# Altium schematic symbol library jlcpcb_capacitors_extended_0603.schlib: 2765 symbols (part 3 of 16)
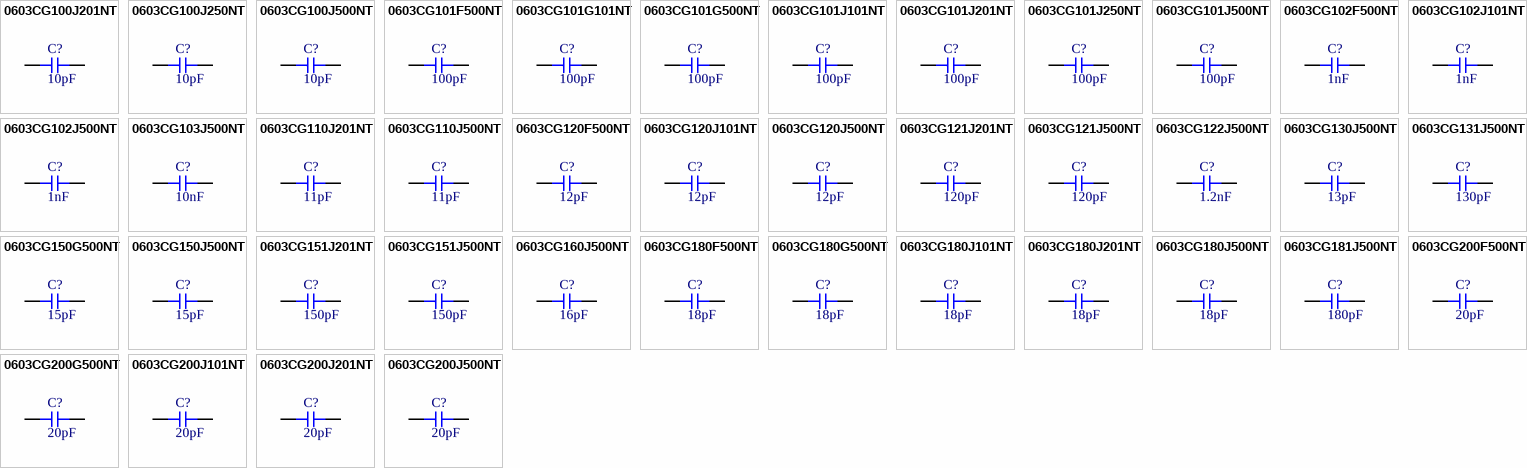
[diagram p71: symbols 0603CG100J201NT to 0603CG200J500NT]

## 0603CG200G500NT
designator C?  Capacitance: 20pF  (hidden comment: *)
Capacitor, Ceramic (MLCC), 20pF, ±2%, 50V, C0G, ±2%, SMD 0603; Manufacturer: FH(Guangdong Fenghua Advanced Tech); Manufacturer Part Number: 0603CG200G500NT
footprint CAP-0603 (0603 (1608M) Capacitor)
pins: 1, 2

## 0603CG200J101NT
designator C?  Capacitance: 20pF  (hidden comment: *)
Capacitor, Ceramic (MLCC), 20pF, ±5%, 100V, C0G, ±5%, SMD 0603; Manufacturer: FH(Guangdong Fenghua Advanced Tech); Manufacturer Part Number: 0603CG200J101NT
footprint CAP-0603 (0603 (1608M) Capacitor)
pins: 1, 2

## 0603CG200J201NT
designator C?  Capacitance: 20pF  (hidden comment: *)
Capacitor, Ceramic (MLCC), 20pF, ±5%, 200V, C0G, ±5%, SMD 0603; Manufacturer: FH(Guangdong Fenghua Advanced Tech); Manufacturer Part Number: 0603CG200J201NT
footprint CAP-0603 (0603 (1608M) Capacitor)
pins: 1, 2

## 0603CG200J500NT
designator C?  Capacitance: 20pF  (hidden comment: *)
Capacitor, Ceramic (MLCC), 20pF, ±5%, 50V, C0G, ±5%, SMD 0603; Manufacturer: FH(Guangdong Fenghua Advanced Tech); Manufacturer Part Number: 0603CG200J500NT
footprint CAP-0603 (0603 (1608M) Capacitor)
pins: 1, 2

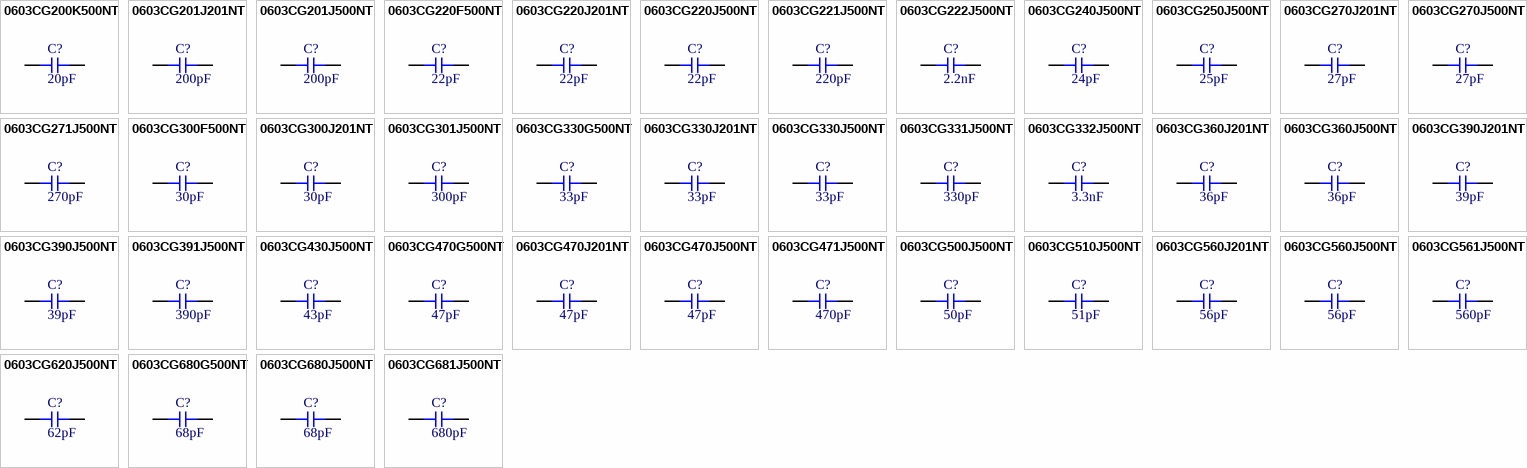
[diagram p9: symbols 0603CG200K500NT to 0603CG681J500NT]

## 0603CG200K500NT
designator C?  Capacitance: 20pF  (hidden comment: *)
Capacitor, Ceramic (MLCC), 20pF, ±10%, 50V, ±10%, SMD 0603; Manufacturer: FH (Guangdong Fenghua Advanced Tech); Manufacturer Part Number: 0603CG200K500NT
footprint CAP-0603 (0603 (1608M) Capacitor)
pins: 1, 2

## 0603CG201J201NT
designator C?  Capacitance: 200pF  (hidden comment: *)
Capacitor, Ceramic (MLCC), 200pF, ±5%, 200V, C0G, ±5%, SMD 0603; Manufacturer: FH(Guangdong Fenghua Advanced Tech); Manufacturer Part Number: 0603CG201J201NT
footprint CAP-0603 (0603 (1608M) Capacitor)
pins: 1, 2

## 0603CG201J500NT
designator C?  Capacitance: 200pF  (hidden comment: *)
Capacitor, Ceramic (MLCC), 200pF, ±5%, 50V, C0G, ±5%, SMD 0603; Manufacturer: FH(Guangdong Fenghua Advanced Tech); Manufacturer Part Number: 0603CG201J500NT
footprint CAP-0603 (0603 (1608M) Capacitor)
pins: 1, 2

## 0603CG220F500NT
designator C?  Capacitance: 22pF  (hidden comment: *)
Capacitor, Ceramic (MLCC), 22pF, ±1%, 50V, C0G, ±1%, SMD 0603; Manufacturer: FH(Guangdong Fenghua Advanced Tech); Manufacturer Part Number: 0603CG220F500NT
footprint CAP-0603 (0603 (1608M) Capacitor)
pins: 1, 2

## 0603CG220J201NT
designator C?  Capacitance: 22pF  (hidden comment: *)
Capacitor, Ceramic (MLCC), 22pF, ±5%, 200V, C0G, ±5%, SMD 0603; Manufacturer: FH(Guangdong Fenghua Advanced Tech); Manufacturer Part Number: 0603CG220J201NT
footprint CAP-0603 (0603 (1608M) Capacitor)
pins: 1, 2

## 0603CG220J500NT
designator C?  Capacitance: 22pF  (hidden comment: *)
Capacitor, Ceramic (MLCC), 22pF, ±5%, 50V, C0G, ±5%, SMD 0603; Manufacturer: FH(Guangdong Fenghua Advanced Tech); Manufacturer Part Number: 0603CG220J500NT
footprint CAP-0603 (0603 (1608M) Capacitor)
pins: 1, 2

## 0603CG221J500NT
designator C?  Capacitance: 220pF  (hidden comment: *)
Capacitor, Ceramic (MLCC), 220pF, ±5%, 50V, C0G, ±5%, SMD 0603; Manufacturer: FH(Guangdong Fenghua Advanced Tech); Manufacturer Part Number: 0603CG221J500NT
footprint CAP-0603 (0603 (1608M) Capacitor)
pins: 1, 2

## 0603CG222J500NT
designator C?  Capacitance: 2.2nF  (hidden comment: *)
Capacitor, Ceramic (MLCC), 2.2nF, ±5%, 50V, C0G, ±5%, SMD 0603; Manufacturer: FH(Guangdong Fenghua Advanced Tech); Manufacturer Part Number: 0603CG222J500NT
footprint CAP-0603 (0603 (1608M) Capacitor)
pins: 1, 2

## 0603CG240J500NT
designator C?  Capacitance: 24pF  (hidden comment: *)
Capacitor, Ceramic (MLCC), 24pF, ±5%, 50V, C0G, ±5%, SMD 0603; Manufacturer: FH(Guangdong Fenghua Advanced Tech); Manufacturer Part Number: 0603CG240J500NT
footprint CAP-0603 (0603 (1608M) Capacitor)
pins: 1, 2

## 0603CG250J500NT
designator C?  Capacitance: 25pF  (hidden comment: *)
Capacitor, Ceramic (MLCC), 25pF, ±5%, 50V, C0G, ±5%, SMD 0603; Manufacturer: FH(Guangdong Fenghua Advanced Tech); Manufacturer Part Number: 0603CG250J500NT
footprint CAP-0603 (0603 (1608M) Capacitor)
pins: 1, 2

## 0603CG270J201NT
designator C?  Capacitance: 27pF  (hidden comment: *)
Capacitor, Ceramic (MLCC), 27pF, ±5%, 200V, C0G, ±5%, SMD 0603; Manufacturer: FH(Guangdong Fenghua Advanced Tech); Manufacturer Part Number: 0603CG270J201NT
footprint CAP-0603 (0603 (1608M) Capacitor)
pins: 1, 2

## 0603CG270J500NT
designator C?  Capacitance: 27pF  (hidden comment: *)
Capacitor, Ceramic (MLCC), 27pF, ±5%, 50V, C0G, ±5%, SMD 0603; Manufacturer: FH(Guangdong Fenghua Advanced Tech); Manufacturer Part Number: 0603CG270J500NT
footprint CAP-0603 (0603 (1608M) Capacitor)
pins: 1, 2

## 0603CG271J500NT
designator C?  Capacitance: 270pF  (hidden comment: *)
Capacitor, Ceramic (MLCC), 270pF, ±5%, 50V, C0G, ±5%, SMD 0603; Manufacturer: FH(Guangdong Fenghua Advanced Tech); Manufacturer Part Number: 0603CG271J500NT
footprint CAP-0603 (0603 (1608M) Capacitor)
pins: 1, 2

## 0603CG300F500NT
designator C?  Capacitance: 30pF  (hidden comment: *)
Capacitor, Ceramic (MLCC), 30pF, ±1%, 50V, C0G, ±1%, SMD 0603; Manufacturer: FH(Guangdong Fenghua Advanced Tech); Manufacturer Part Number: 0603CG300F500NT
footprint CAP-0603 (0603 (1608M) Capacitor)
pins: 1, 2

## 0603CG300J201NT
designator C?  Capacitance: 30pF  (hidden comment: *)
Capacitor, Ceramic (MLCC), 30pF, ±5%, 200V, C0G, ±5%, SMD 0603; Manufacturer: FH(Guangdong Fenghua Advanced Tech); Manufacturer Part Number: 0603CG300J201NT
footprint CAP-0603 (0603 (1608M) Capacitor)
pins: 1, 2

## 0603CG301J500NT
designator C?  Capacitance: 300pF  (hidden comment: *)
Capacitor, Ceramic (MLCC), 300pF, ±5%, 50V, C0G, ±5%, SMD 0603; Manufacturer: FH(Guangdong Fenghua Advanced Tech); Manufacturer Part Number: 0603CG301J500NT
footprint CAP-0603 (0603 (1608M) Capacitor)
pins: 1, 2

## 0603CG330G500NT
designator C?  Capacitance: 33pF  (hidden comment: *)
Capacitor, Ceramic (MLCC), 33pF, ±2%, 50V, C0G, ±2%, SMD 0603; Manufacturer: FH(Guangdong Fenghua Advanced Tech); Manufacturer Part Number: 0603CG330G500NT
footprint CAP-0603 (0603 (1608M) Capacitor)
pins: 1, 2

## 0603CG330J201NT
designator C?  Capacitance: 33pF  (hidden comment: *)
Capacitor, Ceramic (MLCC), 33pF, ±5%, 200V, C0G, ±5%, SMD 0603; Manufacturer: FH(Guangdong Fenghua Advanced Tech); Manufacturer Part Number: 0603CG330J201NT
footprint CAP-0603 (0603 (1608M) Capacitor)
pins: 1, 2

## 0603CG330J500NT
designator C?  Capacitance: 33pF  (hidden comment: *)
Capacitor, Ceramic (MLCC), 33pF, ±5%, 50V, C0G, ±5%, SMD 0603; Manufacturer: FH(Guangdong Fenghua Advanced Tech); Manufacturer Part Number: 0603CG330J500NT
footprint CAP-0603 (0603 (1608M) Capacitor)
pins: 1, 2

## 0603CG331J500NT
designator C?  Capacitance: 330pF  (hidden comment: *)
Capacitor, Ceramic (MLCC), 330pF, ±5%, 50V, C0G, ±5%, SMD 0603; Manufacturer: FH(Guangdong Fenghua Advanced Tech); Manufacturer Part Number: 0603CG331J500NT
footprint CAP-0603 (0603 (1608M) Capacitor)
pins: 1, 2

## 0603CG332J500NT
designator C?  Capacitance: 3.3nF  (hidden comment: *)
Capacitor, Ceramic (MLCC), 3.3nF, ±5%, 50V, C0G, ±5%, SMD 0603; Manufacturer: FH(Guangdong Fenghua Advanced Tech); Manufacturer Part Number: 0603CG332J500NT
footprint CAP-0603 (0603 (1608M) Capacitor)
pins: 1, 2

## 0603CG360J201NT
designator C?  Capacitance: 36pF  (hidden comment: *)
Capacitor, Ceramic (MLCC), 36pF, ±5%, 200V, C0G, ±5%, SMD 0603; Manufacturer: FH(Guangdong Fenghua Advanced Tech); Manufacturer Part Number: 0603CG360J201NT
footprint CAP-0603 (0603 (1608M) Capacitor)
pins: 1, 2

## 0603CG360J500NT
designator C?  Capacitance: 36pF  (hidden comment: *)
Capacitor, Ceramic (MLCC), 36pF, ±5%, 50V, C0G, ±5%, SMD 0603; Manufacturer: FH(Guangdong Fenghua Advanced Tech); Manufacturer Part Number: 0603CG360J500NT
footprint CAP-0603 (0603 (1608M) Capacitor)
pins: 1, 2

## 0603CG390J201NT
designator C?  Capacitance: 39pF  (hidden comment: *)
Capacitor, Ceramic (MLCC), 39pF, ±5%, 200V, C0G, ±5%, SMD 0603; Manufacturer: FH(Guangdong Fenghua Advanced Tech); Manufacturer Part Number: 0603CG390J201NT
footprint CAP-0603 (0603 (1608M) Capacitor)
pins: 1, 2

## 0603CG390J500NT
designator C?  Capacitance: 39pF  (hidden comment: *)
Capacitor, Ceramic (MLCC), 39pF, ±5%, 50V, C0G, ±5%, SMD 0603; Manufacturer: FH(Guangdong Fenghua Advanced Tech); Manufacturer Part Number: 0603CG390J500NT
footprint CAP-0603 (0603 (1608M) Capacitor)
pins: 1, 2

## 0603CG391J500NT
designator C?  Capacitance: 390pF  (hidden comment: *)
Capacitor, Ceramic (MLCC), 390pF, ±5%, 50V, C0G, ±5%, SMD 0603; Manufacturer: FH(Guangdong Fenghua Advanced Tech); Manufacturer Part Number: 0603CG391J500NT
footprint CAP-0603 (0603 (1608M) Capacitor)
pins: 1, 2

## 0603CG430J500NT
designator C?  Capacitance: 43pF  (hidden comment: *)
Capacitor, Ceramic (MLCC), 43pF, ±5%, 50V, C0G, ±5%, SMD 0603; Manufacturer: FH(Guangdong Fenghua Advanced Tech); Manufacturer Part Number: 0603CG430J500NT
footprint CAP-0603 (0603 (1608M) Capacitor)
pins: 1, 2

## 0603CG470G500NT
designator C?  Capacitance: 47pF  (hidden comment: *)
Capacitor, Ceramic (MLCC), 47pF, ±2%, 50V, C0G, ±2%, SMD 0603; Manufacturer: FH(Guangdong Fenghua Advanced Tech); Manufacturer Part Number: 0603CG470G500NT
footprint CAP-0603 (0603 (1608M) Capacitor)
pins: 1, 2

## 0603CG470J201NT
designator C?  Capacitance: 47pF  (hidden comment: *)
Capacitor, Ceramic (MLCC), 47pF, ±5%, 200V, C0G, ±5%, SMD 0603; Manufacturer: FH(Guangdong Fenghua Advanced Tech); Manufacturer Part Number: 0603CG470J201NT
footprint CAP-0603 (0603 (1608M) Capacitor)
pins: 1, 2

## 0603CG470J500NT
designator C?  Capacitance: 47pF  (hidden comment: *)
Capacitor, Ceramic (MLCC), 47pF, ±5%, 50V, C0G, ±5%, SMD 0603; Manufacturer: FH(Guangdong Fenghua Advanced Tech); Manufacturer Part Number: 0603CG470J500NT
footprint CAP-0603 (0603 (1608M) Capacitor)
pins: 1, 2

## 0603CG471J500NT
designator C?  Capacitance: 470pF  (hidden comment: *)
Capacitor, Ceramic (MLCC), 470pF, ±5%, 50V, C0G, ±5%, SMD 0603; Manufacturer: FH(Guangdong Fenghua Advanced Tech); Manufacturer Part Number: 0603CG471J500NT
footprint CAP-0603 (0603 (1608M) Capacitor)
pins: 1, 2

## 0603CG500J500NT
designator C?  Capacitance: 50pF  (hidden comment: *)
Capacitor, Ceramic (MLCC), 50pF, ±5%, 50V, C0G, ±5%, SMD 0603; Manufacturer: FH(Guangdong Fenghua Advanced Tech); Manufacturer Part Number: 0603CG500J500NT
footprint CAP-0603 (0603 (1608M) Capacitor)
pins: 1, 2

## 0603CG510J500NT
designator C?  Capacitance: 51pF  (hidden comment: *)
Capacitor, Ceramic (MLCC), 51pF, ±5%, 50V, C0G, ±5%, SMD 0603; Manufacturer: FH(Guangdong Fenghua Advanced Tech); Manufacturer Part Number: 0603CG510J500NT
footprint CAP-0603 (0603 (1608M) Capacitor)
pins: 1, 2

## 0603CG560J201NT
designator C?  Capacitance: 56pF  (hidden comment: *)
Capacitor, Ceramic (MLCC), 56pF, ±5%, 200V, C0G, ±5%, SMD 0603; Manufacturer: FH(Guangdong Fenghua Advanced Tech); Manufacturer Part Number: 0603CG560J201NT
footprint CAP-0603 (0603 (1608M) Capacitor)
pins: 1, 2

## 0603CG560J500NT
designator C?  Capacitance: 56pF  (hidden comment: *)
Capacitor, Ceramic (MLCC), 56pF, ±5%, 50V, C0G, ±5%, SMD 0603; Manufacturer: FH(Guangdong Fenghua Advanced Tech); Manufacturer Part Number: 0603CG560J500NT
footprint CAP-0603 (0603 (1608M) Capacitor)
pins: 1, 2

## 0603CG561J500NT
designator C?  Capacitance: 560pF  (hidden comment: *)
Capacitor, Ceramic (MLCC), 560pF, ±5%, 50V, C0G, ±5%, SMD 0603; Manufacturer: FH(Guangdong Fenghua Advanced Tech); Manufacturer Part Number: 0603CG561J500NT
footprint CAP-0603 (0603 (1608M) Capacitor)
pins: 1, 2

## 0603CG620J500NT
designator C?  Capacitance: 62pF  (hidden comment: *)
Capacitor, Ceramic (MLCC), 62pF, ±5%, 50V, C0G, ±5%, SMD 0603; Manufacturer: FH(Guangdong Fenghua Advanced Tech); Manufacturer Part Number: 0603CG620J500NT
footprint CAP-0603 (0603 (1608M) Capacitor)
pins: 1, 2

## 0603CG680G500NT
designator C?  Capacitance: 68pF  (hidden comment: *)
Capacitor, Ceramic (MLCC), 68pF, ±2%, 50V, C0G, ±2%, SMD 0603; Manufacturer: FH(Guangdong Fenghua Advanced Tech); Manufacturer Part Number: 0603CG680G500NT
footprint CAP-0603 (0603 (1608M) Capacitor)
pins: 1, 2

## 0603CG680J500NT
designator C?  Capacitance: 68pF  (hidden comment: *)
Capacitor, Ceramic (MLCC), 68pF, ±5%, 50V, C0G, ±5%, SMD 0603; Manufacturer: FH(Guangdong Fenghua Advanced Tech); Manufacturer Part Number: 0603CG680J500NT
footprint CAP-0603 (0603 (1608M) Capacitor)
pins: 1, 2

## 0603CG681J500NT
designator C?  Capacitance: 680pF  (hidden comment: *)
Capacitor, Ceramic (MLCC), 680pF, ±5%, 50V, C0G, ±5%, SMD 0603; Manufacturer: FH(Guangdong Fenghua Advanced Tech); Manufacturer Part Number: 0603CG681J500NT
footprint CAP-0603 (0603 (1608M) Capacitor)
pins: 1, 2

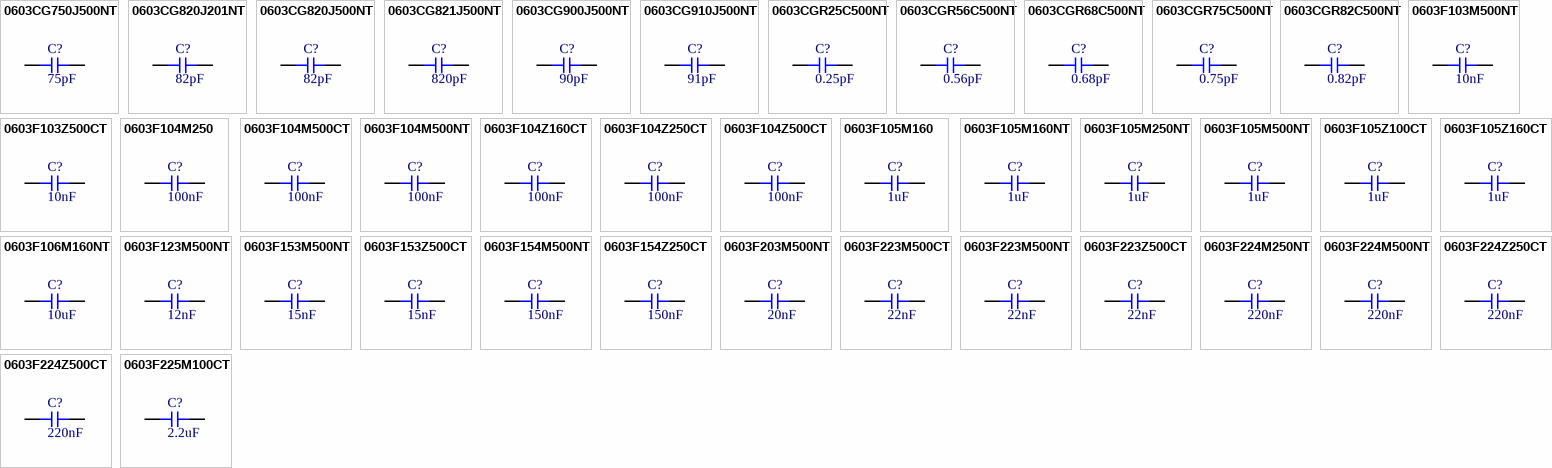
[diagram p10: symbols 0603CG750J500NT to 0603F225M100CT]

## 0603CG750J500NT
designator C?  Capacitance: 75pF  (hidden comment: *)
Capacitor, Ceramic (MLCC), 75pF, ±5%, 50V, C0G, ±5%, SMD 0603; Manufacturer: FH(Guangdong Fenghua Advanced Tech); Manufacturer Part Number: 0603CG750J500NT
footprint CAP-0603 (0603 (1608M) Capacitor)
pins: 1, 2

## 0603CG820J201NT
designator C?  Capacitance: 82pF  (hidden comment: *)
Capacitor, Ceramic (MLCC), 82pF, ±5%, 200V, C0G, ±5%, SMD 0603; Manufacturer: FH(Guangdong Fenghua Advanced Tech); Manufacturer Part Number: 0603CG820J201NT
footprint CAP-0603 (0603 (1608M) Capacitor)
pins: 1, 2

## 0603CG820J500NT
designator C?  Capacitance: 82pF  (hidden comment: *)
Capacitor, Ceramic (MLCC), 82pF, ±5%, 50V, C0G, ±5%, SMD 0603; Manufacturer: FH(Guangdong Fenghua Advanced Tech); Manufacturer Part Number: 0603CG820J500NT
footprint CAP-0603 (0603 (1608M) Capacitor)
pins: 1, 2

## 0603CG821J500NT
designator C?  Capacitance: 820pF  (hidden comment: *)
Capacitor, Ceramic (MLCC), 820pF, ±5%, 50V, C0G, ±5%, SMD 0603; Manufacturer: FH(Guangdong Fenghua Advanced Tech); Manufacturer Part Number: 0603CG821J500NT
footprint CAP-0603 (0603 (1608M) Capacitor)
pins: 1, 2

## 0603CG900J500NT
designator C?  Capacitance: 90pF  (hidden comment: *)
Capacitor, Ceramic (MLCC), 90pF, ±5%, 50V, C0G, ±5%, SMD 0603; Manufacturer: FH(Guangdong Fenghua Advanced Tech); Manufacturer Part Number: 0603CG900J500NT
footprint CAP-0603 (0603 (1608M) Capacitor)
pins: 1, 2

## 0603CG910J500NT
designator C?  Capacitance: 91pF  (hidden comment: *)
Capacitor, Ceramic (MLCC), 91pF, ±5%, 50V, C0G, ±5%, SMD 0603; Manufacturer: FH(Guangdong Fenghua Advanced Tech); Manufacturer Part Number: 0603CG910J500NT
footprint CAP-0603 (0603 (1608M) Capacitor)
pins: 1, 2

## 0603CGR25C500NT
designator C?  Capacitance: 0.25pF  (hidden comment: *)
Capacitor, Ceramic (MLCC), 0.25pF, ±0.25pF, 50V, C0G, ±0.25pF, SMD 0603; Manufacturer: FH(Guangdong Fenghua Advanced Tech); Manufacturer Part Number: 0603CGR25C500NT
footprint CAP-0603 (0603 (1608M) Capacitor)
pins: 1, 2

## 0603CGR56C500NT
designator C?  Capacitance: 0.56pF  (hidden comment: *)
Capacitor, Ceramic (MLCC), 0.56pF, ±0.25pF, 50V, C0G, ±0.25pF, SMD 0603; Manufacturer: FH(Guangdong Fenghua Advanced Tech); Manufacturer Part Number: 0603CGR56C500NT
footprint CAP-0603 (0603 (1608M) Capacitor)
pins: 1, 2

## 0603CGR68C500NT
designator C?  Capacitance: 0.68pF  (hidden comment: *)
Capacitor, Ceramic (MLCC), 0.68pF, ±0.25pF, 50V, C0G, ±0.25pF, SMD 0603; Manufacturer: FH(Guangdong Fenghua Advanced Tech); Manufacturer Part Number: 0603CGR68C500NT
footprint CAP-0603 (0603 (1608M) Capacitor)
pins: 1, 2

## 0603CGR75C500NT
designator C?  Capacitance: 0.75pF  (hidden comment: *)
Capacitor, Ceramic (MLCC), 0.75pF, ±0.25pF, 50V, C0G, ±0.25pF, SMD 0603; Manufacturer: FH(Guangdong Fenghua Advanced Tech); Manufacturer Part Number: 0603CGR75C500NT
footprint CAP-0603 (0603 (1608M) Capacitor)
pins: 1, 2

## 0603CGR82C500NT
designator C?  Capacitance: 0.82pF  (hidden comment: *)
Capacitor, Ceramic (MLCC), 0.82pF, ±0.25pF, 50V, C0G, ±0.25pF, SMD 0603; Manufacturer: FH(Guangdong Fenghua Advanced Tech); Manufacturer Part Number: 0603CGR82C500NT
footprint CAP-0603 (0603 (1608M) Capacitor)
pins: 1, 2

## 0603F103M500NT
designator C?  Capacitance: 10nF  (hidden comment: *)
Capacitor, Ceramic (MLCC), 10nF, ±20%, 50V, Y5V, ±20%, SMD 0603; Manufacturer: FH(Guangdong Fenghua Advanced Tech); Manufacturer Part Number: 0603F103M500NT
footprint CAP-0603 (0603 (1608M) Capacitor)
pins: 1, 2

## 0603F103Z500CT
designator C?  Capacitance: 10nF  (hidden comment: *)
Capacitor, Ceramic (MLCC), 10nF, 50V, Y5V, SMD 0603; Manufacturer: Walsin Tech Corp; Manufacturer Part Number: 0603F103Z500CT; Temperature Rating: -20%~+80%
footprint CAP-0603 (0603 (1608M) Capacitor)
pins: 1, 2

## 0603F104M250
designator C?  Capacitance: 100nF  (hidden comment: *)
Capacitor, Ceramic (MLCC), 100nF, ±20%, 25V, Y5V, ±20%, SMD 0603; Manufacturer: Walsin Tech Corp; Manufacturer Part Number: 0603F104M250
footprint CAP-0603 (0603 (1608M) Capacitor)
pins: 1, 2

## 0603F104M500CT
designator C?  Capacitance: 100nF  (hidden comment: *)
Capacitor, Ceramic (MLCC), 100nF, ±20%, 50V, Y5V, ±20%, SMD 0603; Manufacturer: Walsin Tech Corp; Manufacturer Part Number: 0603F104M500CT
footprint CAP-0603 (0603 (1608M) Capacitor)
pins: 1, 2

## 0603F104M500NT
designator C?  Capacitance: 100nF  (hidden comment: *)
Capacitor, Ceramic (MLCC), 100nF, ±20%, 50V, Y5V, ±20%, SMD 0603; Manufacturer: FH(Guangdong Fenghua Advanced Tech); Manufacturer Part Number: 0603F104M500NT
footprint CAP-0603 (0603 (1608M) Capacitor)
pins: 1, 2

## 0603F104Z160CT
designator C?  Capacitance: 100nF  (hidden comment: *)
Capacitor, Ceramic (MLCC), 100nF, 16V, Y5V, SMD 0603; Manufacturer: Walsin Tech Corp; Manufacturer Part Number: 0603F104Z160CT; Temperature Rating: -20%~+80%
footprint CAP-0603 (0603 (1608M) Capacitor)
pins: 1, 2

## 0603F104Z250CT
designator C?  Capacitance: 100nF  (hidden comment: *)
Capacitor, Ceramic (MLCC), 100nF, 25V, Y5V, SMD 0603; Manufacturer: Walsin Tech Corp; Manufacturer Part Number: 0603F104Z250CT; Temperature Rating: -20%~+80%
footprint CAP-0603 (0603 (1608M) Capacitor)
pins: 1, 2

## 0603F104Z500CT
designator C?  Capacitance: 100nF  (hidden comment: *)
Capacitor, Ceramic (MLCC), 100nF, 50V, Y5V, SMD 0603; Manufacturer: Walsin Tech Corp; Manufacturer Part Number: 0603F104Z500CT; Temperature Rating: -20%~+80%
footprint CAP-0603 (0603 (1608M) Capacitor)
pins: 1, 2

## 0603F105M160
designator C?  Capacitance: 1uF  (hidden comment: *)
Capacitor, Ceramic (MLCC), 1uF, ±20%, 16V, Y5V, ±20%, SMD 0603; Manufacturer: Walsin Tech Corp; Manufacturer Part Number: 0603F105M160
footprint CAP-0603 (0603 (1608M) Capacitor)
pins: 1, 2

## 0603F105M160NT
designator C?  Capacitance: 1uF  (hidden comment: *)
Capacitor, Ceramic (MLCC), 1uF, ±20%, 16V, Y5V, ±20%, SMD 0603; Manufacturer: FH(Guangdong Fenghua Advanced Tech); Manufacturer Part Number: 0603F105M160NT
footprint CAP-0603 (0603 (1608M) Capacitor)
pins: 1, 2

## 0603F105M250NT
designator C?  Capacitance: 1uF  (hidden comment: *)
Capacitor, Ceramic (MLCC), 1uF, ±20%, 25V, Y5V, ±20%, SMD 0603; Manufacturer: FH(Guangdong Fenghua Advanced Tech); Manufacturer Part Number: 0603F105M250NT
footprint CAP-0603 (0603 (1608M) Capacitor)
pins: 1, 2

## 0603F105M500NT
designator C?  Capacitance: 1uF  (hidden comment: *)
Capacitor, Ceramic (MLCC), 1uF, ±20%, 50V, Y5V, ±20%, SMD 0603; Manufacturer: FH(Guangdong Fenghua Advanced Tech); Manufacturer Part Number: 0603F105M500NT
footprint CAP-0603 (0603 (1608M) Capacitor)
pins: 1, 2

## 0603F105Z100CT
designator C?  Capacitance: 1uF  (hidden comment: *)
Capacitor, Ceramic (MLCC), 1uF, 10V, Y5V, SMD 0603; Manufacturer: Walsin Tech Corp; Manufacturer Part Number: 0603F105Z100CT; Temperature Rating: -20%~+80%
footprint CAP-0603 (0603 (1608M) Capacitor)
pins: 1, 2

## 0603F105Z160CT
designator C?  Capacitance: 1uF  (hidden comment: *)
Capacitor, Ceramic (MLCC), 1uF, 16V, Y5V, SMD 0603; Manufacturer: Walsin Tech Corp; Manufacturer Part Number: 0603F105Z160CT; Temperature Rating: -20%~+80%
footprint CAP-0603 (0603 (1608M) Capacitor)
pins: 1, 2

## 0603F106M160NT
designator C?  Capacitance: 10uF  (hidden comment: *)
Capacitor, Ceramic (MLCC), 10uF, ±20%, 16V, Y5V, ±20%, SMD 0603; Manufacturer: FH(Guangdong Fenghua Advanced Tech); Manufacturer Part Number: 0603F106M160NT
footprint CAP-0603 (0603 (1608M) Capacitor)
pins: 1, 2

## 0603F123M500NT
designator C?  Capacitance: 12nF  (hidden comment: *)
Capacitor, Ceramic (MLCC), 12nF, ±20%, 50V, Y5V, ±20%, SMD 0603; Manufacturer: FH(Guangdong Fenghua Advanced Tech); Manufacturer Part Number: 0603F123M500NT
footprint CAP-0603 (0603 (1608M) Capacitor)
pins: 1, 2

## 0603F153M500NT
designator C?  Capacitance: 15nF  (hidden comment: *)
Capacitor, Ceramic (MLCC), 15nF, ±20%, 50V, Y5V, ±20%, SMD 0603; Manufacturer: FH(Guangdong Fenghua Advanced Tech); Manufacturer Part Number: 0603F153M500NT
footprint CAP-0603 (0603 (1608M) Capacitor)
pins: 1, 2

## 0603F153Z500CT
designator C?  Capacitance: 15nF  (hidden comment: *)
Capacitor, Ceramic (MLCC), 15nF, 50V, Y5V, SMD 0603; Manufacturer: Walsin Tech Corp; Manufacturer Part Number: 0603F153Z500CT; Temperature Rating: -20%~+80%
footprint CAP-0603 (0603 (1608M) Capacitor)
pins: 1, 2

## 0603F154M500NT
designator C?  Capacitance: 150nF  (hidden comment: *)
Capacitor, Ceramic (MLCC), 150nF, ±20%, 50V, Y5V, ±20%, SMD 0603; Manufacturer: FH(Guangdong Fenghua Advanced Tech); Manufacturer Part Number: 0603F154M500NT
footprint CAP-0603 (0603 (1608M) Capacitor)
pins: 1, 2

## 0603F154Z250CT
designator C?  Capacitance: 150nF  (hidden comment: *)
Capacitor, Ceramic (MLCC), 150nF, 25V, Y5V, SMD 0603; Manufacturer: Walsin Tech Corp; Manufacturer Part Number: 0603F154Z250CT; Temperature Rating: -20%~+80%
footprint CAP-0603 (0603 (1608M) Capacitor)
pins: 1, 2

## 0603F203M500NT
designator C?  Capacitance: 20nF  (hidden comment: *)
Capacitor, Ceramic (MLCC), 20nF, ±20%, 50V, Y5V, ±20%, SMD 0603; Manufacturer: FH(Guangdong Fenghua Advanced Tech); Manufacturer Part Number: 0603F203M500NT
footprint CAP-0603 (0603 (1608M) Capacitor)
pins: 1, 2

## 0603F223M500CT
designator C?  Capacitance: 22nF  (hidden comment: *)
Capacitor, Ceramic (MLCC), 22nF, ±20%, 50V, Y5V, ±20%, SMD 0603; Manufacturer: Walsin Tech Corp; Manufacturer Part Number: 0603F223M500CT
footprint CAP-0603 (0603 (1608M) Capacitor)
pins: 1, 2

## 0603F223M500NT
designator C?  Capacitance: 22nF  (hidden comment: *)
Capacitor, Ceramic (MLCC), 22nF, ±20%, 50V, Y5V, ±20%, SMD 0603; Manufacturer: FH(Guangdong Fenghua Advanced Tech); Manufacturer Part Number: 0603F223M500NT
footprint CAP-0603 (0603 (1608M) Capacitor)
pins: 1, 2

## 0603F223Z500CT
designator C?  Capacitance: 22nF  (hidden comment: *)
Capacitor, Ceramic (MLCC), 22nF, 50V, Y5V, SMD 0603; Manufacturer: Walsin Tech Corp; Manufacturer Part Number: 0603F223Z500CT; Temperature Rating: -20%~+80%
footprint CAP-0603 (0603 (1608M) Capacitor)
pins: 1, 2

## 0603F224M250NT
designator C?  Capacitance: 220nF  (hidden comment: *)
Capacitor, Ceramic (MLCC), 220nF, ±20%, 25V, Y5V, ±20%, SMD 0603; Manufacturer: FH(Guangdong Fenghua Advanced Tech); Manufacturer Part Number: 0603F224M250NT
footprint CAP-0603 (0603 (1608M) Capacitor)
pins: 1, 2

## 0603F224M500NT
designator C?  Capacitance: 220nF  (hidden comment: *)
Capacitor, Ceramic (MLCC), 220nF, ±20%, 50V, Y5V, ±20%, SMD 0603; Manufacturer: FH(Guangdong Fenghua Advanced Tech); Manufacturer Part Number: 0603F224M500NT
footprint CAP-0603 (0603 (1608M) Capacitor)
pins: 1, 2

## 0603F224Z250CT
designator C?  Capacitance: 220nF  (hidden comment: *)
Capacitor, Ceramic (MLCC), 220nF, 25V, Y5V, SMD 0603; Manufacturer: Walsin Tech Corp; Manufacturer Part Number: 0603F224Z250CT; Temperature Rating: -20%~+80%
footprint CAP-0603 (0603 (1608M) Capacitor)
pins: 1, 2

## 0603F224Z500CT
designator C?  Capacitance: 220nF  (hidden comment: *)
Capacitor, Ceramic (MLCC), 220nF, 50V, Y5V, SMD 0603; Manufacturer: Walsin Tech Corp; Manufacturer Part Number: 0603F224Z500CT; Temperature Rating: -20%~+80%
footprint CAP-0603 (0603 (1608M) Capacitor)
pins: 1, 2

## 0603F225M100CT
designator C?  Capacitance: 2.2uF  (hidden comment: *)
Capacitor, Ceramic (MLCC), 2.2uF, ±20%, 10V, Y5V, ±20%, SMD 0603; Manufacturer: Walsin Tech Corp; Manufacturer Part Number: 0603F225M100CT
footprint CAP-0603 (0603 (1608M) Capacitor)
pins: 1, 2

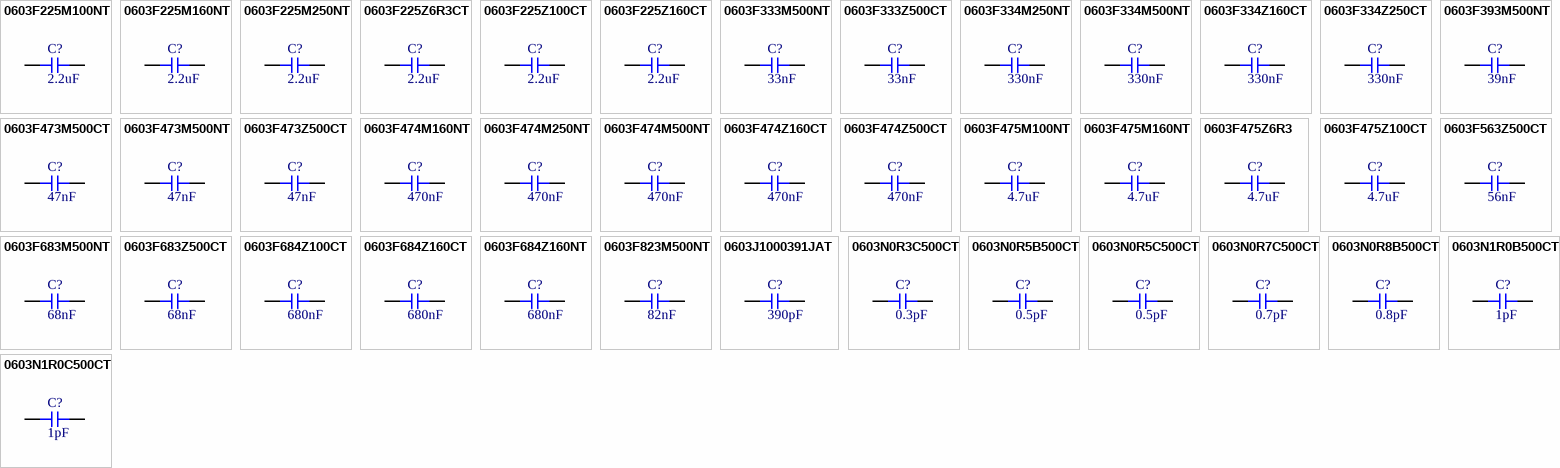
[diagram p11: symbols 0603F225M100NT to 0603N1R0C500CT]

## 0603F225M100NT
designator C?  Capacitance: 2.2uF  (hidden comment: *)
Capacitor, Ceramic (MLCC), 2.2uF, ±20%, 10V, Y5V, ±20%, SMD 0603; Manufacturer: FH(Guangdong Fenghua Advanced Tech); Manufacturer Part Number: 0603F225M100NT
footprint CAP-0603 (0603 (1608M) Capacitor)
pins: 1, 2

## 0603F225M160NT
designator C?  Capacitance: 2.2uF  (hidden comment: *)
Capacitor, Ceramic (MLCC), 2.2uF, ±20%, 16V, Y5V, ±20%, SMD 0603; Manufacturer: FH(Guangdong Fenghua Advanced Tech); Manufacturer Part Number: 0603F225M160NT
footprint CAP-0603 (0603 (1608M) Capacitor)
pins: 1, 2

## 0603F225M250NT
designator C?  Capacitance: 2.2uF  (hidden comment: *)
Capacitor, Ceramic (MLCC), 2.2uF, ±20%, 25V, Y5V, ±20%, SMD 0603; Manufacturer: FH(Guangdong Fenghua Advanced Tech); Manufacturer Part Number: 0603F225M250NT
footprint CAP-0603 (0603 (1608M) Capacitor)
pins: 1, 2

## 0603F225Z6R3CT
designator C?  Capacitance: 2.2uF  (hidden comment: *)
Capacitor, Ceramic (MLCC), 2.2uF, 6.3V, Y5V, SMD 0603; Manufacturer: Walsin Tech Corp; Manufacturer Part Number: 0603F225Z6R3CT; Temperature Rating: -20%~+80%
footprint CAP-0603 (0603 (1608M) Capacitor)
pins: 1, 2

## 0603F225Z100CT
designator C?  Capacitance: 2.2uF  (hidden comment: *)
Capacitor, Ceramic (MLCC), 2.2uF, 10V, Y5V, SMD 0603; Manufacturer: Walsin Tech Corp; Manufacturer Part Number: 0603F225Z100CT; Temperature Rating: -20%~+80%
footprint CAP-0603 (0603 (1608M) Capacitor)
pins: 1, 2

## 0603F225Z160CT
designator C?  Capacitance: 2.2uF  (hidden comment: *)
Capacitor, Ceramic (MLCC), 2.2uF, 16V, Y5V, SMD 0603; Manufacturer: Walsin Tech Corp; Manufacturer Part Number: 0603F225Z160CT; Temperature Rating: -20%~+80%
footprint CAP-0603 (0603 (1608M) Capacitor)
pins: 1, 2

## 0603F333M500NT
designator C?  Capacitance: 33nF  (hidden comment: *)
Capacitor, Ceramic (MLCC), 33nF, ±20%, 50V, Y5V, ±20%, SMD 0603; Manufacturer: FH(Guangdong Fenghua Advanced Tech); Manufacturer Part Number: 0603F333M500NT
footprint CAP-0603 (0603 (1608M) Capacitor)
pins: 1, 2

## 0603F333Z500CT
designator C?  Capacitance: 33nF  (hidden comment: *)
Capacitor, Ceramic (MLCC), 33nF, 50V, Y5V, SMD 0603; Manufacturer: Walsin Tech Corp; Manufacturer Part Number: 0603F333Z500CT; Temperature Rating: -20%~+80%
footprint CAP-0603 (0603 (1608M) Capacitor)
pins: 1, 2

## 0603F334M250NT
designator C?  Capacitance: 330nF  (hidden comment: *)
Capacitor, Ceramic (MLCC), 330nF, ±20%, 25V, Y5V, ±20%, SMD 0603; Manufacturer: FH(Guangdong Fenghua Advanced Tech); Manufacturer Part Number: 0603F334M250NT
footprint CAP-0603 (0603 (1608M) Capacitor)
pins: 1, 2

## 0603F334M500NT
designator C?  Capacitance: 330nF  (hidden comment: *)
Capacitor, Ceramic (MLCC), 330nF, ±20%, 50V, Y5V, ±20%, SMD 0603; Manufacturer: FH(Guangdong Fenghua Advanced Tech); Manufacturer Part Number: 0603F334M500NT
footprint CAP-0603 (0603 (1608M) Capacitor)
pins: 1, 2

## 0603F334Z160CT
designator C?  Capacitance: 330nF  (hidden comment: *)
Capacitor, Ceramic (MLCC), 330nF, 16V, Y5V, SMD 0603; Manufacturer: Walsin Tech Corp; Manufacturer Part Number: 0603F334Z160CT; Temperature Rating: -20%~+80%
footprint CAP-0603 (0603 (1608M) Capacitor)
pins: 1, 2

## 0603F334Z250CT
designator C?  Capacitance: 330nF  (hidden comment: *)
Capacitor, Ceramic (MLCC), 330nF, 25V, Y5V, SMD 0603; Manufacturer: Walsin Tech Corp; Manufacturer Part Number: 0603F334Z250CT; Temperature Rating: -20%~+80%
footprint CAP-0603 (0603 (1608M) Capacitor)
pins: 1, 2

## 0603F393M500NT
designator C?  Capacitance: 39nF  (hidden comment: *)
Capacitor, Ceramic (MLCC), 39nF, ±20%, 50V, Y5V, ±20%, SMD 0603; Manufacturer: FH(Guangdong Fenghua Advanced Tech); Manufacturer Part Number: 0603F393M500NT
footprint CAP-0603 (0603 (1608M) Capacitor)
pins: 1, 2

## 0603F473M500CT
designator C?  Capacitance: 47nF  (hidden comment: *)
Capacitor, Ceramic (MLCC), 47nF, ±20%, 50V, Y5V, ±20%, SMD 0603; Manufacturer: Walsin Tech Corp; Manufacturer Part Number: 0603F473M500CT
footprint CAP-0603 (0603 (1608M) Capacitor)
pins: 1, 2

## 0603F473M500NT
designator C?  Capacitance: 47nF  (hidden comment: *)
Capacitor, Ceramic (MLCC), 47nF, ±20%, 50V, Y5V, ±20%, SMD 0603; Manufacturer: FH(Guangdong Fenghua Advanced Tech); Manufacturer Part Number: 0603F473M500NT
footprint CAP-0603 (0603 (1608M) Capacitor)
pins: 1, 2

## 0603F473Z500CT
designator C?  Capacitance: 47nF  (hidden comment: *)
Capacitor, Ceramic (MLCC), 47nF, 50V, Y5V, SMD 0603; Manufacturer: Walsin Tech Corp; Manufacturer Part Number: 0603F473Z500CT; Temperature Rating: -20%~+80%
footprint CAP-0603 (0603 (1608M) Capacitor)
pins: 1, 2

## 0603F474M160NT
designator C?  Capacitance: 470nF  (hidden comment: *)
Capacitor, Ceramic (MLCC), 470nF, ±20%, 16V, Y5V, ±20%, SMD 0603; Manufacturer: FH(Guangdong Fenghua Advanced Tech); Manufacturer Part Number: 0603F474M160NT
footprint CAP-0603 (0603 (1608M) Capacitor)
pins: 1, 2

## 0603F474M250NT
designator C?  Capacitance: 470nF  (hidden comment: *)
Capacitor, Ceramic (MLCC), 470nF, ±20%, 25V, Y5V, ±20%, SMD 0603; Manufacturer: FH(Guangdong Fenghua Advanced Tech); Manufacturer Part Number: 0603F474M250NT
footprint CAP-0603 (0603 (1608M) Capacitor)
pins: 1, 2

## 0603F474M500NT
designator C?  Capacitance: 470nF  (hidden comment: *)
Capacitor, Ceramic (MLCC), 470nF, ±20%, 50V, Y5V, ±20%, SMD 0603; Manufacturer: FH(Guangdong Fenghua Advanced Tech); Manufacturer Part Number: 0603F474M500NT
footprint CAP-0603 (0603 (1608M) Capacitor)
pins: 1, 2

## 0603F474Z160CT
designator C?  Capacitance: 470nF  (hidden comment: *)
Capacitor, Ceramic (MLCC), 470nF, 16V, Y5V, SMD 0603; Manufacturer: Walsin Tech Corp; Manufacturer Part Number: 0603F474Z160CT; Temperature Rating: -20%~+80%
footprint CAP-0603 (0603 (1608M) Capacitor)
pins: 1, 2

## 0603F474Z500CT
designator C?  Capacitance: 470nF  (hidden comment: *)
Capacitor, Ceramic (MLCC), 470nF, 50V, Y5V, SMD 0603; Manufacturer: Walsin Tech Corp; Manufacturer Part Number: 0603F474Z500CT; Temperature Rating: -20%~+80%
footprint CAP-0603 (0603 (1608M) Capacitor)
pins: 1, 2

## 0603F475M100NT
designator C?  Capacitance: 4.7uF  (hidden comment: *)
Capacitor, Ceramic (MLCC), 4.7uF, ±20%, 10V, Y5V, ±20%, SMD 0603; Manufacturer: FH(Guangdong Fenghua Advanced Tech); Manufacturer Part Number: 0603F475M100NT
footprint CAP-0603 (0603 (1608M) Capacitor)
pins: 1, 2

## 0603F475M160NT
designator C?  Capacitance: 4.7uF  (hidden comment: *)
Capacitor, Ceramic (MLCC), 4.7uF, ±20%, 16V, Y5V, ±20%, SMD 0603; Manufacturer: FH(Guangdong Fenghua Advanced Tech); Manufacturer Part Number: 0603F475M160NT
footprint CAP-0603 (0603 (1608M) Capacitor)
pins: 1, 2

## 0603F475Z6R3
designator C?  Capacitance: 4.7uF  (hidden comment: *)
Capacitor, Ceramic (MLCC), 4.7uF, 6.3V, Y5V, SMD 0603; Manufacturer: Walsin Tech Corp; Manufacturer Part Number: 0603F475Z6R3; Temperature Rating: -20%~+80%
footprint CAP-0603 (0603 (1608M) Capacitor)
pins: 1, 2

## 0603F475Z100CT
designator C?  Capacitance: 4.7uF  (hidden comment: *)
Capacitor, Ceramic (MLCC), 4.7uF, 10V, Y5V, SMD 0603; Manufacturer: Walsin Tech Corp; Manufacturer Part Number: 0603F475Z100CT; Temperature Rating: -20%~+80%
footprint CAP-0603 (0603 (1608M) Capacitor)
pins: 1, 2

## 0603F563Z500CT
designator C?  Capacitance: 56nF  (hidden comment: *)
Capacitor, Ceramic (MLCC), 56nF, 50V, Y5V, SMD 0603; Manufacturer: Walsin Tech Corp; Manufacturer Part Number: 0603F563Z500CT; Temperature Rating: -20%~+80%
footprint CAP-0603 (0603 (1608M) Capacitor)
pins: 1, 2

## 0603F683M500NT
designator C?  Capacitance: 68nF  (hidden comment: *)
Capacitor, Ceramic (MLCC), 68nF, ±20%, 50V, Y5V, ±20%, SMD 0603; Manufacturer: FH(Guangdong Fenghua Advanced Tech); Manufacturer Part Number: 0603F683M500NT
footprint CAP-0603 (0603 (1608M) Capacitor)
pins: 1, 2

## 0603F683Z500CT
designator C?  Capacitance: 68nF  (hidden comment: *)
Capacitor, Ceramic (MLCC), 68nF, 50V, Y5V, SMD 0603; Manufacturer: Walsin Tech Corp; Manufacturer Part Number: 0603F683Z500CT; Temperature Rating: -20%~+80%
footprint CAP-0603 (0603 (1608M) Capacitor)
pins: 1, 2

## 0603F684Z100CT
designator C?  Capacitance: 680nF  (hidden comment: *)
Capacitor, Ceramic (MLCC), 680nF, 10V, Y5V, SMD 0603; Manufacturer: Walsin Tech Corp; Manufacturer Part Number: 0603F684Z100CT; Temperature Rating: -20%~+80%
footprint CAP-0603 (0603 (1608M) Capacitor)
pins: 1, 2

## 0603F684Z160CT
designator C?  Capacitance: 680nF  (hidden comment: *)
Capacitor, Ceramic (MLCC), 680nF, 16V, Y5V, SMD 0603; Manufacturer: Walsin Tech Corp; Manufacturer Part Number: 0603F684Z160CT; Temperature Rating: -20%~+80%
footprint CAP-0603 (0603 (1608M) Capacitor)
pins: 1, 2

## 0603F684Z160NT
designator C?  Capacitance: 680nF  (hidden comment: *)
Capacitor, Ceramic (MLCC), 680nF, 16V, Y5V, SMD 0603; Manufacturer: FH(Guangdong Fenghua Advanced Tech); Manufacturer Part Number: 0603F684Z160NT; Temperature Rating: -20%~+80%
footprint CAP-0603 (0603 (1608M) Capacitor)
pins: 1, 2

## 0603F823M500NT
designator C?  Capacitance: 82nF  (hidden comment: *)
Capacitor, Ceramic (MLCC), 82nF, ±20%, 50V, Y5V, ±20%, SMD 0603; Manufacturer: FH(Guangdong Fenghua Advanced Tech); Manufacturer Part Number: 0603F823M500NT
footprint CAP-0603 (0603 (1608M) Capacitor)
pins: 1, 2

## 0603J1000391JAT
designator C?  Capacitance: 390pF  (hidden comment: *)
Capacitor, Ceramic (MLCC), 390pF, ±5%, 100V, C0G, ±5%, SMD 0603; Manufacturer: Knowles; Manufacturer Part Number: 0603J1000391JAT
footprint CAP-0603 (0603 (1608M) Capacitor)
pins: 1, 2

## 0603N0R3C500CT
designator C?  Capacitance: 0.3pF  (hidden comment: *)
Capacitor, Ceramic (MLCC), 0.3pF, ±0.25pF, 50V, NP0, ±0.25pF, SMD 0603; Manufacturer: Walsin Tech Corp; Manufacturer Part Number: 0603N0R3C500CT
footprint CAP-0603 (0603 (1608M) Capacitor)
pins: 1, 2

## 0603N0R5B500CT
designator C?  Capacitance: 0.5pF  (hidden comment: *)
Capacitor, Ceramic (MLCC), 0.5pF, ±0.1pF, 50V, NP0, ±0.1pF, SMD 0603; Manufacturer: Walsin Tech Corp; Manufacturer Part Number: 0603N0R5B500CT
footprint CAP-0603 (0603 (1608M) Capacitor)
pins: 1, 2

## 0603N0R5C500CT
designator C?  Capacitance: 0.5pF  (hidden comment: *)
Capacitor, Ceramic (MLCC), 0.5pF, ±0.25pF, 50V, NP0, ±0.25pF, SMD 0603; Manufacturer: Walsin Tech Corp; Manufacturer Part Number: 0603N0R5C500CT
footprint CAP-0603 (0603 (1608M) Capacitor)
pins: 1, 2

## 0603N0R7C500CT
designator C?  Capacitance: 0.7pF  (hidden comment: *)
Capacitor, Ceramic (MLCC), 0.7pF, ±0.25pF, 50V, NP0, ±0.25pF, SMD 0603; Manufacturer: Walsin Tech Corp; Manufacturer Part Number: 0603N0R7C500CT
footprint CAP-0603 (0603 (1608M) Capacitor)
pins: 1, 2

## 0603N0R8B500CT
designator C?  Capacitance: 0.8pF  (hidden comment: *)
Capacitor, Ceramic (MLCC), 0.8pF, ±0.1pF, 50V, NP0, ±0.1pF, SMD 0603; Manufacturer: Walsin Tech Corp; Manufacturer Part Number: 0603N0R8B500CT
footprint CAP-0603 (0603 (1608M) Capacitor)
pins: 1, 2

## 0603N1R0B500CT
designator C?  Capacitance: 1pF  (hidden comment: *)
Capacitor, Ceramic (MLCC), 1pF, ±0.1pF, 50V, NP0, ±0.1pF, SMD 0603; Manufacturer: Walsin Tech Corp; Manufacturer Part Number: 0603N1R0B500CT
footprint CAP-0603 (0603 (1608M) Capacitor)
pins: 1, 2

## 0603N1R0C500CT
designator C?  Capacitance: 1pF  (hidden comment: *)
Capacitor, Ceramic (MLCC), 1pF, ±0.25pF, 50V, NP0, ±0.25pF, SMD 0603; Manufacturer: Walsin Tech Corp; Manufacturer Part Number: 0603N1R0C500CT
footprint CAP-0603 (0603 (1608M) Capacitor)
pins: 1, 2

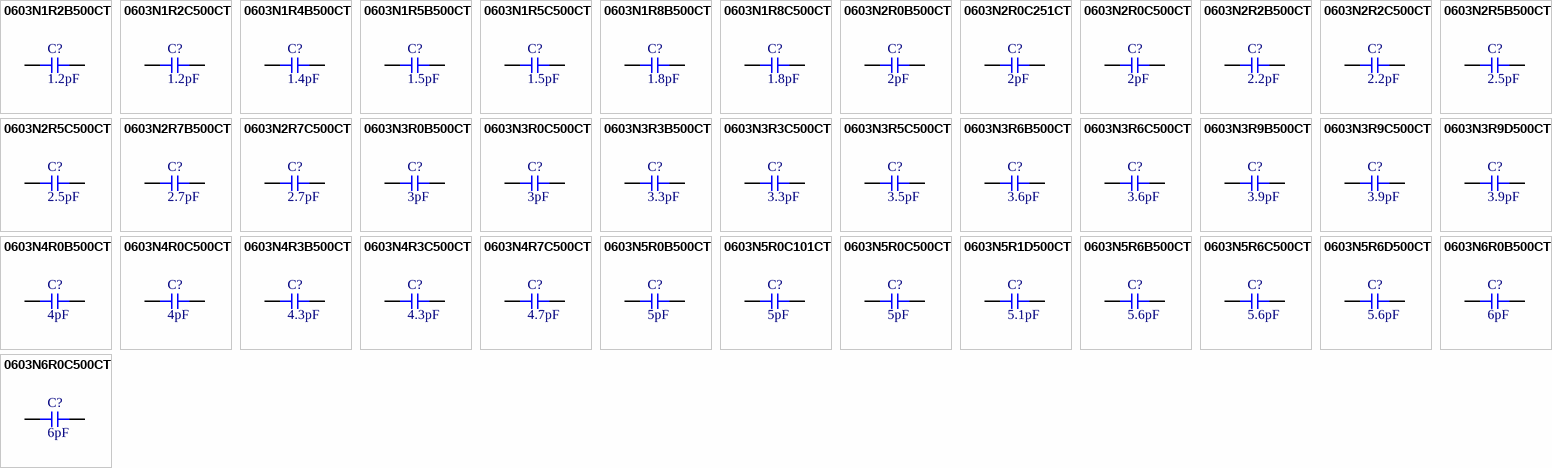
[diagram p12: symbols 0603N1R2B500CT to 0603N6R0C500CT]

## 0603N1R2B500CT
designator C?  Capacitance: 1.2pF  (hidden comment: *)
Capacitor, Ceramic (MLCC), 1.2pF, ±0.1pF, 50V, NP0, ±0.1pF, SMD 0603; Manufacturer: Walsin Tech Corp; Manufacturer Part Number: 0603N1R2B500CT
footprint CAP-0603 (0603 (1608M) Capacitor)
pins: 1, 2

## 0603N1R2C500CT
designator C?  Capacitance: 1.2pF  (hidden comment: *)
Capacitor, Ceramic (MLCC), 1.2pF, ±0.25pF, 50V, NP0, ±0.25pF, SMD 0603; Manufacturer: Walsin Tech Corp; Manufacturer Part Number: 0603N1R2C500CT
footprint CAP-0603 (0603 (1608M) Capacitor)
pins: 1, 2

## 0603N1R4B500CT
designator C?  Capacitance: 1.4pF  (hidden comment: *)
Capacitor, Ceramic (MLCC), 1.4pF, ±0.1pF, 50V, NP0, ±0.1pF, SMD 0603; Manufacturer: Walsin Tech Corp; Manufacturer Part Number: 0603N1R4B500CT
footprint CAP-0603 (0603 (1608M) Capacitor)
pins: 1, 2

## 0603N1R5B500CT
designator C?  Capacitance: 1.5pF  (hidden comment: *)
Capacitor, Ceramic (MLCC), 1.5pF, ±0.1pF, 50V, NP0, ±0.1pF, SMD 0603; Manufacturer: Walsin Tech Corp; Manufacturer Part Number: 0603N1R5B500CT
footprint CAP-0603 (0603 (1608M) Capacitor)
pins: 1, 2

## 0603N1R5C500CT
designator C?  Capacitance: 1.5pF  (hidden comment: *)
Capacitor, Ceramic (MLCC), 1.5pF, ±0.25pF, 50V, NP0, ±0.25pF, SMD 0603; Manufacturer: Walsin Tech Corp; Manufacturer Part Number: 0603N1R5C500CT
footprint CAP-0603 (0603 (1608M) Capacitor)
pins: 1, 2

## 0603N1R8B500CT
designator C?  Capacitance: 1.8pF  (hidden comment: *)
Capacitor, Ceramic (MLCC), 1.8pF, ±0.1pF, 50V, NP0, ±0.1pF, SMD 0603; Manufacturer: Walsin Tech Corp; Manufacturer Part Number: 0603N1R8B500CT
footprint CAP-0603 (0603 (1608M) Capacitor)
pins: 1, 2

## 0603N1R8C500CT
designator C?  Capacitance: 1.8pF  (hidden comment: *)
Capacitor, Ceramic (MLCC), 1.8pF, ±0.25pF, 50V, NP0, ±0.25pF, SMD 0603; Manufacturer: Walsin Tech Corp; Manufacturer Part Number: 0603N1R8C500CT
footprint CAP-0603 (0603 (1608M) Capacitor)
pins: 1, 2

## 0603N2R0B500CT
designator C?  Capacitance: 2pF  (hidden comment: *)
Capacitor, Ceramic (MLCC), 2pF, ±0.1pF, 50V, NP0, ±0.1pF, SMD 0603; Manufacturer: Walsin Tech Corp; Manufacturer Part Number: 0603N2R0B500CT
footprint CAP-0603 (0603 (1608M) Capacitor)
pins: 1, 2

## 0603N2R0C251CT
designator C?  Capacitance: 2pF  (hidden comment: *)
Capacitor, Ceramic (MLCC), 2pF, ±0.25pF, 250V, NP0, ±0.25pF, SMD 0603; Manufacturer: Walsin Tech Corp; Manufacturer Part Number: 0603N2R0C251CT
footprint CAP-0603 (0603 (1608M) Capacitor)
pins: 1, 2

## 0603N2R0C500CT
designator C?  Capacitance: 2pF  (hidden comment: *)
Capacitor, Ceramic (MLCC), 2pF, ±0.25pF, 50V, NP0, ±0.25pF, SMD 0603; Manufacturer: Walsin Tech Corp; Manufacturer Part Number: 0603N2R0C500CT
footprint CAP-0603 (0603 (1608M) Capacitor)
pins: 1, 2

## 0603N2R2B500CT
designator C?  Capacitance: 2.2pF  (hidden comment: *)
Capacitor, Ceramic (MLCC), 2.2pF, ±0.1pF, 50V, NP0, ±0.1pF, SMD 0603; Manufacturer: Walsin Tech Corp; Manufacturer Part Number: 0603N2R2B500CT
footprint CAP-0603 (0603 (1608M) Capacitor)
pins: 1, 2

## 0603N2R2C500CT
designator C?  Capacitance: 2.2pF  (hidden comment: *)
Capacitor, Ceramic (MLCC), 2.2pF, ±0.25pF, 50V, NP0, ±0.25pF, SMD 0603; Manufacturer: Walsin Tech Corp; Manufacturer Part Number: 0603N2R2C500CT
footprint CAP-0603 (0603 (1608M) Capacitor)
pins: 1, 2

## 0603N2R5B500CT
designator C?  Capacitance: 2.5pF  (hidden comment: *)
Capacitor, Ceramic (MLCC), 2.5pF, ±0.1pF, 50V, NP0, ±0.1pF, SMD 0603; Manufacturer: Walsin Tech Corp; Manufacturer Part Number: 0603N2R5B500CT
footprint CAP-0603 (0603 (1608M) Capacitor)
pins: 1, 2

## 0603N2R5C500CT
designator C?  Capacitance: 2.5pF  (hidden comment: *)
Capacitor, Ceramic (MLCC), 2.5pF, ±0.25pF, 50V, NP0, ±0.25pF, SMD 0603; Manufacturer: Walsin Tech Corp; Manufacturer Part Number: 0603N2R5C500CT
footprint CAP-0603 (0603 (1608M) Capacitor)
pins: 1, 2

## 0603N2R7B500CT
designator C?  Capacitance: 2.7pF  (hidden comment: *)
Capacitor, Ceramic (MLCC), 2.7pF, ±0.1pF, 50V, NP0, ±0.1pF, SMD 0603; Manufacturer: Walsin Tech Corp; Manufacturer Part Number: 0603N2R7B500CT
footprint CAP-0603 (0603 (1608M) Capacitor)
pins: 1, 2

## 0603N2R7C500CT
designator C?  Capacitance: 2.7pF  (hidden comment: *)
Capacitor, Ceramic (MLCC), 2.7pF, ±0.25pF, 50V, NP0, ±0.25pF, SMD 0603; Manufacturer: Walsin Tech Corp; Manufacturer Part Number: 0603N2R7C500CT
footprint CAP-0603 (0603 (1608M) Capacitor)
pins: 1, 2

## 0603N3R0B500CT
designator C?  Capacitance: 3pF  (hidden comment: *)
Capacitor, Ceramic (MLCC), 3pF, ±0.1pF, 50V, NP0, ±0.1pF, SMD 0603; Manufacturer: Walsin Tech Corp; Manufacturer Part Number: 0603N3R0B500CT
footprint CAP-0603 (0603 (1608M) Capacitor)
pins: 1, 2

## 0603N3R0C500CT
designator C?  Capacitance: 3pF  (hidden comment: *)
Capacitor, Ceramic (MLCC), 3pF, ±0.25pF, 50V, NP0, ±0.25pF, SMD 0603; Manufacturer: Walsin Tech Corp; Manufacturer Part Number: 0603N3R0C500CT
footprint CAP-0603 (0603 (1608M) Capacitor)
pins: 1, 2

## 0603N3R3B500CT
designator C?  Capacitance: 3.3pF  (hidden comment: *)
Capacitor, Ceramic (MLCC), 3.3pF, ±0.1pF, 50V, NP0, ±0.1pF, SMD 0603; Manufacturer: Walsin Tech Corp; Manufacturer Part Number: 0603N3R3B500CT
footprint CAP-0603 (0603 (1608M) Capacitor)
pins: 1, 2

## 0603N3R3C500CT
designator C?  Capacitance: 3.3pF  (hidden comment: *)
Capacitor, Ceramic (MLCC), 3.3pF, ±0.25pF, 50V, NP0, ±0.25pF, SMD 0603; Manufacturer: Walsin Tech Corp; Manufacturer Part Number: 0603N3R3C500CT
footprint CAP-0603 (0603 (1608M) Capacitor)
pins: 1, 2

## 0603N3R5C500CT
designator C?  Capacitance: 3.5pF  (hidden comment: *)
Capacitor, Ceramic (MLCC), 3.5pF, ±0.25pF, 50V, NP0, ±0.25pF, SMD 0603; Manufacturer: Walsin Tech Corp; Manufacturer Part Number: 0603N3R5C500CT
footprint CAP-0603 (0603 (1608M) Capacitor)
pins: 1, 2

## 0603N3R6B500CT
designator C?  Capacitance: 3.6pF  (hidden comment: *)
Capacitor, Ceramic (MLCC), 3.6pF, ±0.1pF, 50V, NP0, ±0.1pF, SMD 0603; Manufacturer: Walsin Tech Corp; Manufacturer Part Number: 0603N3R6B500CT
footprint CAP-0603 (0603 (1608M) Capacitor)
pins: 1, 2

## 0603N3R6C500CT
designator C?  Capacitance: 3.6pF  (hidden comment: *)
Capacitor, Ceramic (MLCC), 3.6pF, ±0.25pF, 50V, NP0, ±0.25pF, SMD 0603; Manufacturer: Walsin Tech Corp; Manufacturer Part Number: 0603N3R6C500CT
footprint CAP-0603 (0603 (1608M) Capacitor)
pins: 1, 2

## 0603N3R9B500CT
designator C?  Capacitance: 3.9pF  (hidden comment: *)
Capacitor, Ceramic (MLCC), 3.9pF, ±0.1pF, 50V, NP0, ±0.1pF, SMD 0603; Manufacturer: Walsin Tech Corp; Manufacturer Part Number: 0603N3R9B500CT
footprint CAP-0603 (0603 (1608M) Capacitor)
pins: 1, 2

## 0603N3R9C500CT
designator C?  Capacitance: 3.9pF  (hidden comment: *)
Capacitor, Ceramic (MLCC), 3.9pF, ±0.25pF, 50V, NP0, ±0.25pF, SMD 0603; Manufacturer: Walsin Tech Corp; Manufacturer Part Number: 0603N3R9C500CT
footprint CAP-0603 (0603 (1608M) Capacitor)
pins: 1, 2

## 0603N3R9D500CT
designator C?  Capacitance: 3.9pF  (hidden comment: *)
Capacitor, Ceramic (MLCC), 3.9pF, ±0.5pF, 50V, NP0, ±0.5pF, SMD 0603; Manufacturer: Walsin Tech Corp; Manufacturer Part Number: 0603N3R9D500CT
footprint CAP-0603 (0603 (1608M) Capacitor)
pins: 1, 2

## 0603N4R0B500CT
designator C?  Capacitance: 4pF  (hidden comment: *)
Capacitor, Ceramic (MLCC), 4pF, ±0.1pF, 50V, NP0, ±0.1pF, SMD 0603; Manufacturer: Walsin Tech Corp; Manufacturer Part Number: 0603N4R0B500CT
footprint CAP-0603 (0603 (1608M) Capacitor)
pins: 1, 2

## 0603N4R0C500CT
designator C?  Capacitance: 4pF  (hidden comment: *)
Capacitor, Ceramic (MLCC), 4pF, ±0.25pF, 50V, NP0, ±0.25pF, SMD 0603; Manufacturer: Walsin Tech Corp; Manufacturer Part Number: 0603N4R0C500CT
footprint CAP-0603 (0603 (1608M) Capacitor)
pins: 1, 2

## 0603N4R3B500CT
designator C?  Capacitance: 4.3pF  (hidden comment: *)
Capacitor, Ceramic (MLCC), 4.3pF, ±0.1pF, 50V, NP0, ±0.1pF, SMD 0603; Manufacturer: Walsin Tech Corp; Manufacturer Part Number: 0603N4R3B500CT
footprint CAP-0603 (0603 (1608M) Capacitor)
pins: 1, 2

## 0603N4R3C500CT
designator C?  Capacitance: 4.3pF  (hidden comment: *)
Capacitor, Ceramic (MLCC), 4.3pF, ±0.25pF, 50V, NP0, ±0.25pF, SMD 0603; Manufacturer: Walsin Tech Corp; Manufacturer Part Number: 0603N4R3C500CT
footprint CAP-0603 (0603 (1608M) Capacitor)
pins: 1, 2

## 0603N4R7C500CT
designator C?  Capacitance: 4.7pF  (hidden comment: *)
Capacitor, Ceramic (MLCC), 4.7pF, ±0.25pF, 50V, NP0, ±0.25pF, SMD 0603; Manufacturer: Walsin Tech Corp; Manufacturer Part Number: 0603N4R7C500CT
footprint CAP-0603 (0603 (1608M) Capacitor)
pins: 1, 2

## 0603N5R0B500CT
designator C?  Capacitance: 5pF  (hidden comment: *)
Capacitor, Ceramic (MLCC), 5pF, ±0.1pF, 50V, NP0, ±0.1pF, SMD 0603; Manufacturer: Walsin Tech Corp; Manufacturer Part Number: 0603N5R0B500CT
footprint CAP-0603 (0603 (1608M) Capacitor)
pins: 1, 2

## 0603N5R0C101CT
designator C?  Capacitance: 5pF  (hidden comment: *)
Capacitor, Ceramic (MLCC), 5pF, ±0.25pF, 100V, NP0, ±0.25pF, SMD 0603; Manufacturer: Walsin Tech Corp; Manufacturer Part Number: 0603N5R0C101CT
footprint CAP-0603 (0603 (1608M) Capacitor)
pins: 1, 2

## 0603N5R0C500CT
designator C?  Capacitance: 5pF  (hidden comment: *)
Capacitor, Ceramic (MLCC), 5pF, ±0.25pF, 50V, NP0, ±0.25pF, SMD 0603; Manufacturer: Walsin Tech Corp; Manufacturer Part Number: 0603N5R0C500CT
footprint CAP-0603 (0603 (1608M) Capacitor)
pins: 1, 2

## 0603N5R1D500CT
designator C?  Capacitance: 5.1pF  (hidden comment: *)
Capacitor, Ceramic (MLCC), 5.1pF, ±0.5pF, 50V, NP0, ±0.5pF, SMD 0603; Manufacturer: Walsin Tech Corp; Manufacturer Part Number: 0603N5R1D500CT
footprint CAP-0603 (0603 (1608M) Capacitor)
pins: 1, 2

## 0603N5R6B500CT
designator C?  Capacitance: 5.6pF  (hidden comment: *)
Capacitor, Ceramic (MLCC), 5.6pF, ±0.1pF, 50V, NP0, ±0.1pF, SMD 0603; Manufacturer: Walsin Tech Corp; Manufacturer Part Number: 0603N5R6B500CT
footprint CAP-0603 (0603 (1608M) Capacitor)
pins: 1, 2

## 0603N5R6C500CT
designator C?  Capacitance: 5.6pF  (hidden comment: *)
Capacitor, Ceramic (MLCC), 5.6pF, ±0.25pF, 50V, NP0, ±0.25pF, SMD 0603; Manufacturer: Walsin Tech Corp; Manufacturer Part Number: 0603N5R6C500CT
footprint CAP-0603 (0603 (1608M) Capacitor)
pins: 1, 2

## 0603N5R6D500CT
designator C?  Capacitance: 5.6pF  (hidden comment: *)
Capacitor, Ceramic (MLCC), 5.6pF, ±0.5pF, 50V, NP0, ±0.5pF, SMD 0603; Manufacturer: Walsin Tech Corp; Manufacturer Part Number: 0603N5R6D500CT
footprint CAP-0603 (0603 (1608M) Capacitor)
pins: 1, 2

## 0603N6R0B500CT
designator C?  Capacitance: 6pF  (hidden comment: *)
Capacitor, Ceramic (MLCC), 6pF, ±0.1pF, 50V, NP0, ±0.1pF, SMD 0603; Manufacturer: Walsin Tech Corp; Manufacturer Part Number: 0603N6R0B500CT
footprint CAP-0603 (0603 (1608M) Capacitor)
pins: 1, 2

## 0603N6R0C500CT
designator C?  Capacitance: 6pF  (hidden comment: *)
Capacitor, Ceramic (MLCC), 6pF, ±0.25pF, 50V, NP0, ±0.25pF, SMD 0603; Manufacturer: Walsin Tech Corp; Manufacturer Part Number: 0603N6R0C500CT
footprint CAP-0603 (0603 (1608M) Capacitor)
pins: 1, 2

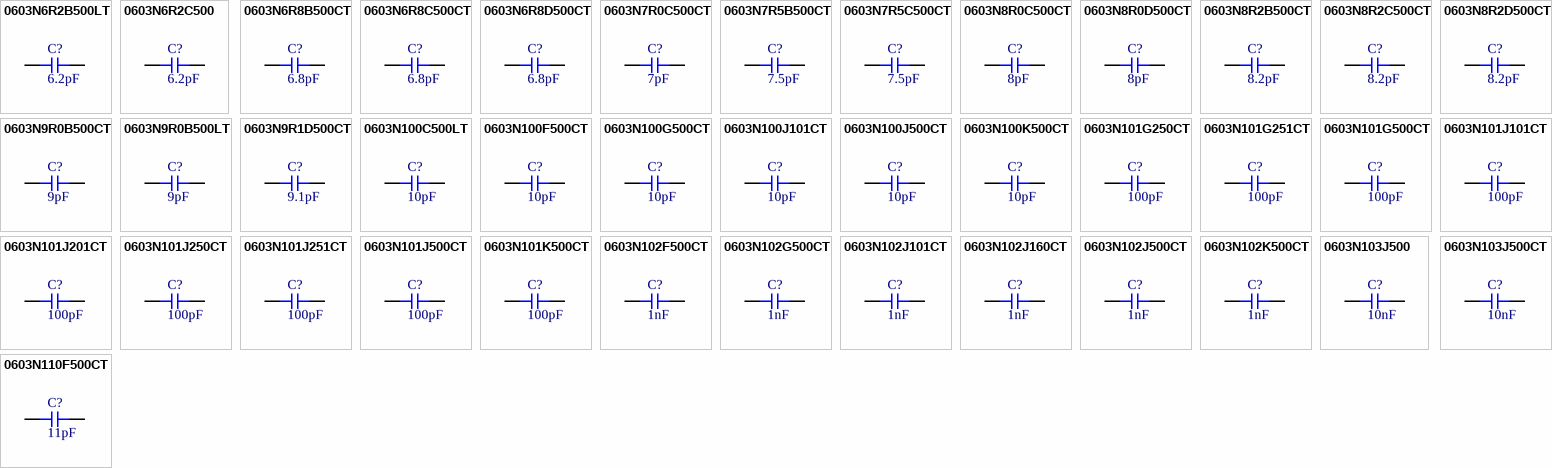
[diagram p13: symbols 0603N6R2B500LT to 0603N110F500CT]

## 0603N6R2B500LT
designator C?  Capacitance: 6.2pF  (hidden comment: *)
Capacitor, Ceramic (MLCC), 6.2pF, ±0.1pF, 50V, NP0, ±0.1pF, SMD 0603; Manufacturer: Walsin Tech Corp; Manufacturer Part Number: 0603N6R2B500LT
footprint CAP-0603 (0603 (1608M) Capacitor)
pins: 1, 2

## 0603N6R2C500
designator C?  Capacitance: 6.2pF  (hidden comment: *)
Capacitor, Ceramic (MLCC), 6.2pF, ±0.25pF, 50V, NP0, ±0.25pF, SMD 0603; Manufacturer: Walsin Tech Corp; Manufacturer Part Number: 0603N6R2C500
footprint CAP-0603 (0603 (1608M) Capacitor)
pins: 1, 2

## 0603N6R8B500CT
designator C?  Capacitance: 6.8pF  (hidden comment: *)
Capacitor, Ceramic (MLCC), 6.8pF, ±0.1pF, 50V, NP0, ±0.1pF, SMD 0603; Manufacturer: Walsin Tech Corp; Manufacturer Part Number: 0603N6R8B500CT
footprint CAP-0603 (0603 (1608M) Capacitor)
pins: 1, 2

## 0603N6R8C500CT
designator C?  Capacitance: 6.8pF  (hidden comment: *)
Capacitor, Ceramic (MLCC), 6.8pF, ±0.25pF, 50V, NP0, ±0.25pF, SMD 0603; Manufacturer: Walsin Tech Corp; Manufacturer Part Number: 0603N6R8C500CT
footprint CAP-0603 (0603 (1608M) Capacitor)
pins: 1, 2

## 0603N6R8D500CT
designator C?  Capacitance: 6.8pF  (hidden comment: *)
Capacitor, Ceramic (MLCC), 6.8pF, ±0.5pF, 50V, NP0, ±0.5pF, SMD 0603; Manufacturer: Walsin Tech Corp; Manufacturer Part Number: 0603N6R8D500CT
footprint CAP-0603 (0603 (1608M) Capacitor)
pins: 1, 2

## 0603N7R0C500CT
designator C?  Capacitance: 7pF  (hidden comment: *)
Capacitor, Ceramic (MLCC), 7pF, ±0.25pF, 50V, NP0, ±0.25pF, SMD 0603; Manufacturer: Walsin Tech Corp; Manufacturer Part Number: 0603N7R0C500CT
footprint CAP-0603 (0603 (1608M) Capacitor)
pins: 1, 2

## 0603N7R5B500CT
designator C?  Capacitance: 7.5pF  (hidden comment: *)
Capacitor, Ceramic (MLCC), 7.5pF, ±0.1pF, 50V, NP0, ±0.1pF, SMD 0603; Manufacturer: Walsin Tech Corp; Manufacturer Part Number: 0603N7R5B500CT
footprint CAP-0603 (0603 (1608M) Capacitor)
pins: 1, 2

## 0603N7R5C500CT
designator C?  Capacitance: 7.5pF  (hidden comment: *)
Capacitor, Ceramic (MLCC), 7.5pF, ±0.25pF, 50V, NP0, ±0.25pF, SMD 0603; Manufacturer: Walsin Tech Corp; Manufacturer Part Number: 0603N7R5C500CT
footprint CAP-0603 (0603 (1608M) Capacitor)
pins: 1, 2

## 0603N8R0C500CT
designator C?  Capacitance: 8pF  (hidden comment: *)
Capacitor, Ceramic (MLCC), 8pF, ±0.25pF, 50V, NP0, ±0.25pF, SMD 0603; Manufacturer: Walsin Tech Corp; Manufacturer Part Number: 0603N8R0C500CT
footprint CAP-0603 (0603 (1608M) Capacitor)
pins: 1, 2

## 0603N8R0D500CT
designator C?  Capacitance: 8pF  (hidden comment: *)
Capacitor, Ceramic (MLCC), 8pF, ±0.5pF, 50V, NP0, ±0.5pF, SMD 0603; Manufacturer: Walsin Tech Corp; Manufacturer Part Number: 0603N8R0D500CT
footprint CAP-0603 (0603 (1608M) Capacitor)
pins: 1, 2

## 0603N8R2B500CT
designator C?  Capacitance: 8.2pF  (hidden comment: *)
Capacitor, Ceramic (MLCC), 8.2pF, ±0.1pF, 50V, NP0, ±0.1pF, SMD 0603; Manufacturer: Walsin Tech Corp; Manufacturer Part Number: 0603N8R2B500CT
footprint CAP-0603 (0603 (1608M) Capacitor)
pins: 1, 2

## 0603N8R2C500CT
designator C?  Capacitance: 8.2pF  (hidden comment: *)
Capacitor, Ceramic (MLCC), 8.2pF, ±0.25pF, 50V, NP0, ±0.25pF, SMD 0603; Manufacturer: Walsin Tech Corp; Manufacturer Part Number: 0603N8R2C500CT
footprint CAP-0603 (0603 (1608M) Capacitor)
pins: 1, 2

## 0603N8R2D500CT
designator C?  Capacitance: 8.2pF  (hidden comment: *)
Capacitor, Ceramic (MLCC), 8.2pF, ±0.5pF, 50V, NP0, ±0.5pF, SMD 0603; Manufacturer: Walsin Tech Corp; Manufacturer Part Number: 0603N8R2D500CT
footprint CAP-0603 (0603 (1608M) Capacitor)
pins: 1, 2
